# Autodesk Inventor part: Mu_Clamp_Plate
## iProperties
Shininess: 64.0
Length Units: 11272
Angle Units: 11279
Time Units: 11290
Mass Units: 11286
Length Display Precision: 3
Angle Display Precision: 2
Compacted: True
Part Number: Mu_Clamp_Plate
Document SubType Name: Modeling
Created: 2004-08
Designer: John Blackburn
Material: Aluminum-6061
Manufacturer: Standard
Standards Organization: Custom
Density: 0.0
Volumn: 0.0
Area: 0.0
PropertySet Name: Model Information
Control State: 0
Master: False
Checked Out: False
Author: John Blackburn
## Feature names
1. Extrusion1
2. Hole1
